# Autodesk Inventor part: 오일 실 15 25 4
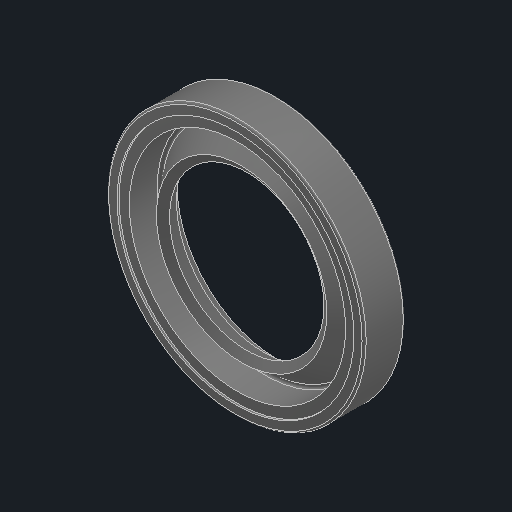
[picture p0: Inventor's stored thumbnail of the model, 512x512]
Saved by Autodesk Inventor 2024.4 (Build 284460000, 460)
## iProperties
Created: 2025-10
Part Number: 오일 실 15 25 4
Material: 고무
Description: 오일 실 - 비스프링, 조립 GA
Document SubType Name: Modeling
Designer: user
Density: 0.93 g/cm^3
Appearance: 기본값
Author: jhkim
Sending System: Autodesk Inventor 2026
Preprocessor: ST-DEVELOPER v20.1
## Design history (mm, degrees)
feature "Solid1"
node "솔리드1"
